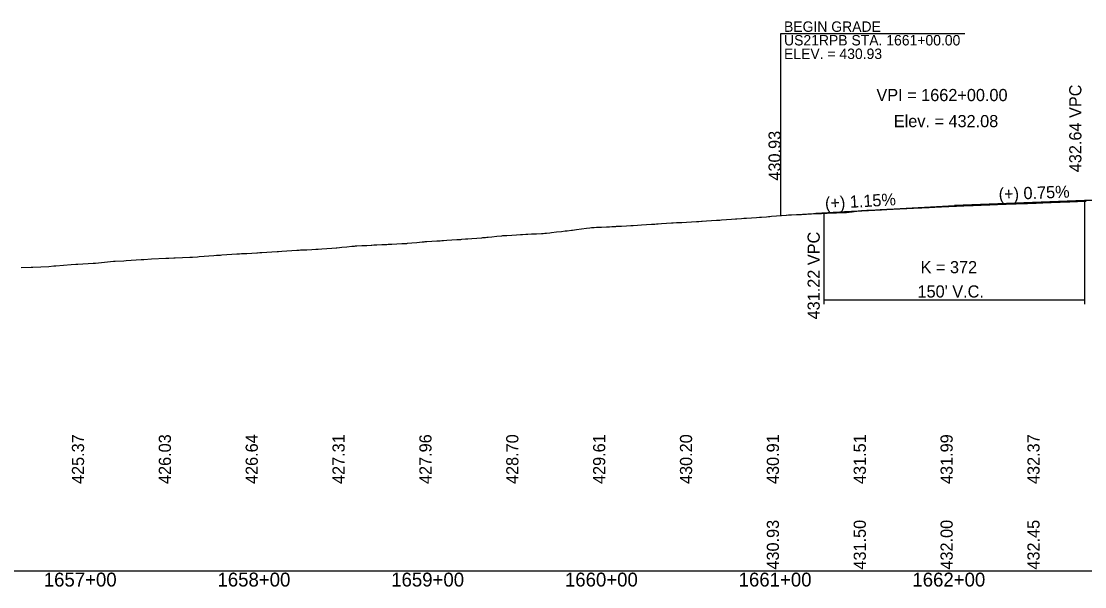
# Model space of a CAD drawing. Extents: x 2017200 to 2047700, y 854850 to 893350.
# Drawn here: x 2021863 to 2022475, y 883091 to 883416 of the extents above; entities that cross this region are included whole.
import ezdxf

# ---------------------------------------------------------------- set-up
doc = ezdxf.new("R2010")
doc.units = 0
for name, color, linetype in [('RD_DDB_GradeTX', 7, 'Continuous'), ('RD_DDB_Profile_EX', 7, 'Continuous'), ('RD_DDB_Profile_Lbl', 7, 'Continuous'), ('RD_DDB_Profile_PR', 7, 'Continuous'), ('RD_DDB_StaTX', 7, 'Continuous'), ('RD_DDB_StripGrade', 7, 'Continuous'), ('RD_DDB_VCLbl', 7, 'Continuous'), ('RD_GPK_Profile_Cell', 7, 'Continuous')]:
    doc.layers.add(name, color=color, linetype=linetype)

msp = doc.modelspace()

# ---------------------------------------------------------------- linework, layer by layer
at = {"layer": 'RD_DDB_GradeTX'}
for p, q in [((2022479.94, 883313.39), (2022400, 883310.4)), ((2022470.06, 883313.02), (2022550, 883316)), ((2022320.13, 883305.81), (2022400, 883310.4))]:
    msp.add_line(p, q, dxfattribs=at)
at = {"layer": 'RD_DDB_Profile_EX'}
msp.add_lwpolyline([(2021862.75, 883274.56), (2021868.48, 883274.81), (2021869.53, 883274.88), (2021878.68, 883275.29), (2021881.69, 883275.52), (2021882.79, 883275.63), (2021891.66, 883276.33), (2021894.2, 883276.46), (2021895.46, 883276.59), (2021904.21, 883277.05), (2021905.57, 883277.11), (2021907.28, 883277.29), (2021915.85, 883278.18), (2021916.97, 883278.23), (2021921.82, 883278.56), (2021923.32, 883278.63), (2021931.8, 883279.2), (2021933.35, 883279.28), (2021937.74, 883279.53), (2021946.1, 883280.01), (2021947.75, 883280.08), (2021950.73, 883280.2), (2021951.47, 883280.23), (2021959.83, 883280.56), (2021961.47, 883280.64), (2021964.23, 883280.84), (2021965.17, 883280.89), (2021973.64, 883281.52), (2021975.15, 883281.64), (2021977.48, 883281.81), (2021978.26, 883281.87), (2021986.87, 883282.47), (2021988.38, 883282.55), (2021989.64, 883282.61), (2021992.73, 883282.78), (2021995.6, 883282.94), (2021998.48, 883283.09), (2021998.84, 883283.1), (2022000.12, 883283.19), (2022001.37, 883283.26), (2022004.23, 883283.45), (2022007.11, 883283.63), (2022010.12, 883283.81), (2022010.88, 883283.86), (2022012.86, 883284), (2022015.73, 883284.2), (2022018.61, 883284.4), (2022021.51, 883284.6), (2022022.77, 883284.67), (2022023.68, 883284.71), (2022024.36, 883284.75), (2022027.23, 883284.88), (2022030.11, 883285.01), (2022032.37, 883285.11), (2022032.99, 883285.16), (2022033.69, 883285.21), (2022035.86, 883285.37), (2022038.74, 883285.57), (2022041.61, 883285.77), (2022044.14, 883285.94), (2022044.49, 883285.98), (2022045.94, 883286.12), (2022047.36, 883286.27), (2022050.24, 883286.59), (2022053.14, 883286.9), (2022054.69, 883286.99), (2022055.25, 883287.02), (2022055.65, 883287.05), (2022055.99, 883287.07), (2022058.87, 883287.22), (2022061.74, 883287.37), (2022064.26, 883287.5), (2022064.62, 883287.52), (2022065.76, 883287.58), (2022067.49, 883287.67), (2022070.37, 883287.82), (2022073.25, 883287.96), (2022074.12, 883288.01), (2022075.32, 883288.07), (2022076.12, 883288.1), (2022079, 883288.23), (2022081.87, 883288.36), (2022082.37, 883288.38), (2022083.23, 883288.35), (2022083.99, 883288.43), (2022084.75, 883288.51), (2022085.14, 883288.55), (2022087.62, 883288.79), (2022090.5, 883289.07), (2022093.58, 883289.36), (2022094.78, 883289.46), (2022095.43, 883289.5), (2022096.25, 883289.55), (2022099.13, 883289.74), (2022102, 883289.92), (2022103.93, 883290.04), (2022104.88, 883290.15), (2022105.19, 883290.18), (2022105.98, 883290.23), (2022107.75, 883290.34), (2022110.63, 883290.51), (2022113.5, 883290.67), (2022114.55, 883290.73), (2022115.88, 883290.82), (2022116.38, 883290.86), (2022118.54, 883291.05), (2022119.26, 883291.09), (2022119.95, 883291.13), (2022122.13, 883291.32), (2022125.01, 883291.56), (2022127.88, 883291.8), (2022128.52, 883291.86), (2022129.15, 883291.89), (2022130.09, 883291.99), (2022130.76, 883292.04), (2022131.54, 883292.1), (2022133.63, 883292.32), (2022136.51, 883292.62), (2022139.38, 883292.91), (2022140.09, 883292.98), (2022141.23, 883293.04), (2022141.58, 883293.07), (2022142.26, 883293.11), (2022145.14, 883293.27), (2022148.01, 883293.42), (2022150.24, 883293.54), (2022150.89, 883293.59), (2022151.3, 883293.63), (2022153.28, 883293.72), (2022153.76, 883293.76), (2022154.42, 883293.82), (2022156.64, 883293.93), (2022159.51, 883294.06), (2022162.39, 883294.19), (2022163.18, 883294.22), (2022164.31, 883294.3), (2022165.27, 883294.42), (2022167.17, 883294.64), (2022168.14, 883294.75), (2022171.02, 883295.08), (2022173.89, 883295.41), (2022175.99, 883295.65), (2022176.77, 883295.7), (2022177.17, 883295.73), (2022179.64, 883296.09), (2022180.16, 883296.16), (2022181.3, 883296.27), (2022182.52, 883296.45), (2022185.4, 883296.86), (2022188.27, 883297.26), (2022190.16, 883297.53), (2022191.15, 883297.58), (2022192.15, 883297.63), (2022192.69, 883297.68), (2022194.02, 883297.75), (2022196.9, 883297.89), (2022199.77, 883298.03), (2022201.44, 883298.11), (2022202.72, 883298.18), (2022205, 883298.3), (2022205.52, 883298.33), (2022208.4, 883298.48), (2022211.28, 883298.63), (2022213.81, 883298.75), (2022214.15, 883298.77), (2022214.99, 883298.82), (2022217.57, 883298.99), (2022219.9, 883299.15), (2022222.78, 883299.34), (2022225.65, 883299.52), (2022226.29, 883299.56), (2022227.58, 883299.66), (2022228.53, 883299.73), (2022229.41, 883299.81), (2022231.41, 883299.95), (2022234.28, 883300.13), (2022237.16, 883300.31), (2022238.12, 883300.37), (2022240.03, 883300.49), (2022242.11, 883300.61), (2022243.09, 883300.62), (2022245.78, 883300.78), (2022248.66, 883300.94), (2022251.53, 883301.1), (2022252.12, 883301.14), (2022252.93, 883301.17), (2022254.41, 883301.27), (2022254.81, 883301.3), (2022257.29, 883301.46), (2022260.16, 883301.65), (2022263.04, 883301.84), (2022263.95, 883301.89), (2022264.91, 883301.95), (2022265.91, 883302.03), (2022268.79, 883302.24), (2022271.66, 883302.44), (2022273.92, 883302.6), (2022274.79, 883302.67), (2022277.42, 883302.85), (2022278.71, 883302.94), (2022280.29, 883303.05), (2022283.17, 883303.24), (2022286.04, 883303.43), (2022287.87, 883303.54), (2022288.92, 883303.63), (2022291.79, 883303.87), (2022292.89, 883303.96), (2022293.67, 883304.03), (2022294.67, 883304.11), (2022297.55, 883304.34), (2022300.42, 883304.57), (2022303.3, 883304.78), (2022304.52, 883304.85), (2022305.25, 883304.89), (2022306.17, 883304.93), (2022309.05, 883305.07), (2022311.92, 883305.21), (2022314.8, 883305.35), (2022316.64, 883305.43), (2022317.67, 883305.5), (2022320.55, 883305.63), (2022323.43, 883305.75), (2022326.3, 883305.88), (2022326.7, 883305.9), (2022329.3, 883306.01), (2022330.16, 883306.05), (2022332.05, 883306.13), (2022334.93, 883306.25), (2022337.8, 883306.37), (2022339.35, 883306.43), (2022340.29, 883306.58), (2022340.68, 883306.63), (2022341.18, 883306.71), (2022343.56, 883307.03), (2022346.44, 883307.38), (2022348.41, 883307.47), (2022349.31, 883307.52), (2022349.82, 883307.54), (2022350.43, 883307.58), (2022352.18, 883307.67), (2022352.55, 883307.69), (2022353.08, 883307.71), (2022354.55, 883307.8), (2022355.12, 883307.83), (2022356.56, 883307.89), (2022357.18, 883307.92), (2022357.93, 883307.96), (2022358.56, 883307.99), (2022359.23, 883308.02), (2022360.81, 883308.1), (2022361.28, 883308.12), (2022362.55, 883308.17), (2022363.35, 883308.21), (2022363.68, 883308.23), (2022364.55, 883308.28), (2022365.44, 883308.33), (2022366.56, 883308.38), (2022367.56, 883308.42), (2022368.55, 883308.48), (2022369.68, 883308.53), (2022370.54, 883308.56), (2022371.84, 883308.62), (2022372.52, 883308.65), (2022374.08, 883308.74), (2022374.5, 883308.77), (2022375.19, 883308.79), (2022376.48, 883308.81), (2022378.06, 883308.89), (2022378.63, 883308.92), (2022379.2, 883308.95), (2022380.63, 883309.02), (2022380.94, 883309.03), (2022381.24, 883309.05), (2022382.63, 883309.13), (2022383.3, 883309.16), (2022383.81, 883309.18), (2022384.62, 883309.21), (2022385.37, 883309.24), (2022386.69, 883309.33), (2022387.48, 883309.37), (2022388.63, 883309.43), (2022389.59, 883309.49), (2022390.62, 883309.54), (2022391.75, 883309.59), (2022392.61, 883309.64), (2022393.99, 883309.7), (2022394.6, 883309.73), (2022395.32, 883309.74), (2022396.74, 883309.77), (2022398.19, 883309.85), (2022398.69, 883309.88), (2022399.22, 883309.91), (2022400.69, 883309.97), (2022401.27, 883309.99), (2022402.69, 883310.05), (2022403.34, 883310.08), (2022403.94, 883310.11), (2022404.69, 883310.15), (2022405.43, 883310.18), (2022406.82, 883310.24), (2022407.59, 883310.28), (2022408.71, 883310.32), (2022409.77, 883310.37), (2022410.7, 883310.41), (2022412.11, 883310.47), (2022412.7, 883310.49), (2022413.3, 883310.51), (2022414.73, 883310.56), (2022415.45, 883310.6), (2022416.37, 883310.64), (2022416.76, 883310.65), (2022418.35, 883310.71), (2022418.76, 883310.72), (2022420.31, 883310.79), (2022420.76, 883310.8), (2022421.2, 883310.82), (2022422.25, 883310.87), (2022422.76, 883310.89), (2022424.17, 883310.93), (2022424.77, 883310.95), (2022426.05, 883311), (2022426.95, 883311.04), (2022427.83, 883311.08), (2022428.79, 883311.12), (2022429.82, 883311.16), (2022430.79, 883311.2), (2022432.79, 883311.25), (2022434.47, 883311.31), (2022434.79, 883311.32), (2022435.58, 883311.35), (2022436.45, 883311.38), (2022436.82, 883311.39), (2022438.45, 883311.44), (2022438.83, 883311.45), (2022440.3, 883311.51), (2022440.85, 883311.52), (2022441.33, 883311.54), (2022442.08, 883311.56), (2022442.81, 883311.59), (2022444.2, 883311.67), (2022444.81, 883311.7), (2022447.08, 883311.74), (2022448.85, 883311.83), (2022449.95, 883311.87), (2022450.53, 883311.89), (2022450.87, 883311.9), (2022452.45, 883311.96), (2022452.9, 883311.98), (2022454.28, 883312.04), (2022454.84, 883312.07), (2022455.71, 883312.11), (2022456.88, 883312.17), (2022458.88, 883312.25), (2022460.89, 883312.31), (2022461.46, 883312.33), (2022462.61, 883312.37), (2022462.91, 883312.38), (2022464.55, 883312.45), (2022464.96, 883312.46), (2022466.42, 883312.52), (2022466.9, 883312.54), (2022467.21, 883312.55), (2022468.9, 883312.6), (2022470.08, 883312.65), (2022470.91, 883312.68), (2022472.96, 883312.8), (2022474.66, 883312.84), (2022474.97, 883312.85), (2022475.83, 883312.87)], dxfattribs=at)
at = {"layer": 'RD_DDB_Profile_Lbl'}
msp.add_lwpolyline([(2022300, 883304.65), (2022300, 883409.27), (2022405.91, 883409.27)], dxfattribs=at)
at = {"layer": 'RD_DDB_Profile_PR'}
msp.add_line((2022300, 883304.65), (2022325, 883306.09), dxfattribs=at)
msp.add_spline([(2022325, 883306.09), (2022328, 883306.26), (2022331, 883306.43), (2022334, 883306.6), (2022337, 883306.77), (2022340, 883306.94), (2022343, 883307.1), (2022346, 883307.27), (2022349, 883307.43), (2022352, 883307.59), (2022355, 883307.75), (2022358, 883307.91), (2022361, 883308.07), (2022364, 883308.23), (2022367, 883308.38), (2022370, 883308.54), (2022373, 883308.69), (2022376, 883308.85), (2022379, 883309), (2022382, 883309.15), (2022385, 883309.3), (2022388, 883309.44), (2022391, 883309.59), (2022394, 883309.74), (2022397, 883309.88), (2022400, 883310.02), (2022403, 883310.16), (2022406, 883310.3), (2022409, 883310.44), (2022412, 883310.58), (2022415, 883310.72), (2022418, 883310.85), (2022421, 883310.99), (2022424, 883311.12), (2022427, 883311.25), (2022430, 883311.38), (2022433, 883311.51), (2022436, 883311.64), (2022439, 883311.77), (2022442, 883311.9), (2022445, 883312.02), (2022448, 883312.14), (2022451, 883312.27), (2022454, 883312.39), (2022457, 883312.51), (2022460, 883312.63), (2022463, 883312.74), (2022466, 883312.86), (2022469, 883312.97), (2022472, 883313.09), (2022475, 883313.2)], degree=3, dxfattribs=at)
at = {"layer": 'RD_DDB_VCLbl'}
for p, q in [((2022475, 883253.59), (2022475, 883313.2)), ((2022325, 883253.59), (2022325, 883306.09)), ((2022325, 883256.09), (2022475, 883256.09))]:
    msp.add_line(p, q, dxfattribs=at)
at = {"layer": 'RD_GPK_Profile_Cell'}
msp.add_line((2020500, 883100), (2023200, 883100), dxfattribs=at)

# ---------------------------------------------------------------- texts
at = {"layer": 'RD_DDB_GradeTX'}
for s, rotation, p in [('(+) 0.75%', 2.13757, (2022425.58, 883313.36)), ('(+) 1.15%', 3.2916, (2022325.68, 883308.13))]:
    msp.add_text(s, height=7, rotation=rotation, dxfattribs=at).set_placement(p)
at = {"layer": 'RD_DDB_Profile_Lbl'}
for s, height, rotation, p in [('BEGIN GRADE', 6, 360, (2022301.92, 883410.27)), ('US21RPB STA. 1661+00.00', 6, 360, (2022301.92, 883402.45)), ('ELEV. = 430.93', 6, 360, (2022301.92, 883394.64)), ('430.93', 7, 90, (2022300, 883324.65))]:
    msp.add_text(s, height=height, rotation=rotation, dxfattribs=at).set_placement(p)
for s, p in [('VPI = 1662+00.00', (2022355.1, 883370.4)), ('Elev. = 432.08', (2022365.11, 883355.4))]:
    msp.add_text(s, height=7, dxfattribs=at).set_placement(p)
at = {"layer": 'RD_DDB_StaTX'}
for s, p in [('1657+00', (2021875.8, 883091)), ('1658+00', (2021975.8, 883091)), ('1659+00', (2022075.8, 883091)), ('1660+00', (2022175.8, 883091)), ('1661+00', (2022275.8, 883091)), ('1662+00', (2022375.8, 883091))]:
    msp.add_text(s, height=8, dxfattribs=at).set_placement(p)
at = {"layer": 'RD_DDB_StripGrade'}
for s, p in [('432.64 VPC', (2022473.08, 883329.45)), ('431.22 VPC', (2022322.47, 883244.74)), ('425.37', (2021899, 883150)), ('426.03', (2021949, 883150)), ('426.64', (2021999, 883150)), ('427.31', (2022049, 883150)), ('427.96', (2022099, 883150)), ('428.70', (2022149, 883150)), ('429.61', (2022199, 883150)), ('430.20', (2022249, 883150)), ('430.91', (2022299, 883150)), ('431.51', (2022349, 883150)), ('431.99', (2022399, 883150)), ('432.37', (2022449, 883150)), ('430.93', (2022299, 883100.75)), ('431.50', (2022349, 883100.75)), ('432.00', (2022399, 883100.75)), ('432.45', (2022449, 883100.75))]:
    msp.add_text(s, height=7, rotation=90, dxfattribs=at).set_placement(p)
at = {"layer": 'RD_DDB_VCLbl'}
for s, p in [('K = 372', (2022380.52, 883271.34)), ("150' V.C.", (2022378.75, 883257.34))]:
    msp.add_text(s, height=7, dxfattribs=at).set_placement(p)

doc.saveas('drawing.dxf')
